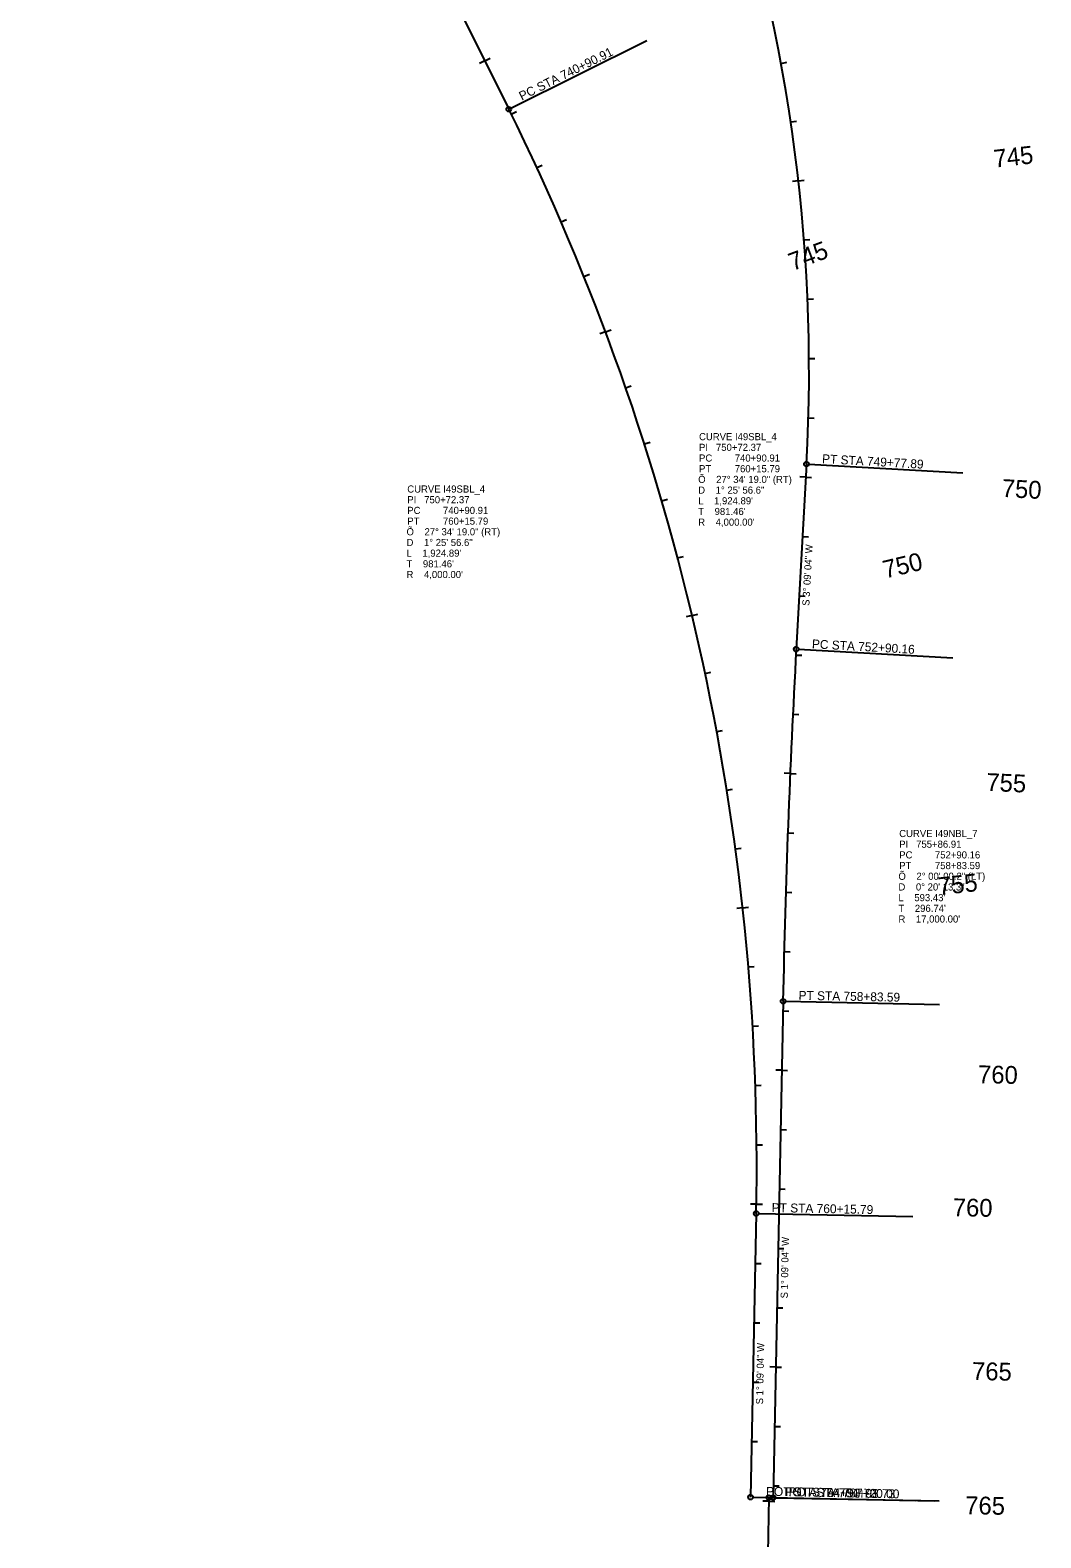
# Model space of a CAD drawing. Extents: x 2819977 to 2827606, y 116785 to 150320.
# Drawn here: x 2822516 to 2824219, y 142313 to 144853 of the extents above; entities that cross this region are included whole.
import ezdxf

# ---------------------------------------------------------------- set-up
doc = ezdxf.new("R2010")
doc.units = 0
for name, color, linetype in [('Default', 7, 'Continuous'), ('Modeling-Contours-Minor-Existing', 7, 'Continuous'), ('Modeling-Flow Arrows-Existing', 7, 'Continuous'), ('Modeling-Spot-Existing', 7, 'Continuous'), ('Modeling-Triangle Verticies-Existing', 7, 'Continuous')]:
    doc.layers.add(name, color=color, linetype=linetype)

msp = doc.modelspace()

# ---------------------------------------------------------------- linework, layer by layer
at = {"layer": 'Default'}
for p, q in [((2822515.7, 146343.3), (2823322.4, 144719.6)), ((2823824, 144121.8), (2823806.8, 143810))]:
    msp.add_line(p, q, dxfattribs=at)
for centre, radius, start, end in [((2820963.6, 144279.3), 2864.8, 356.8489, 41.5661), ((2819740.2, 142939.8), 4000, 358.849, 26.4209), ((2840781.1, 142875.6), 17000, 176.84893, 178.84897)]:
    msp.add_arc(centre, radius, start, end, dxfattribs=at)
at = {"layer": 'Modeling-Flow Arrows-Existing'}
for p, q in [((2822515.7, 146343.3), (2823322.4, 144719.6)), ((2823281.9, 144801), (2823273, 144796.6)), ((2823281.9, 144801), (2823290.9, 144805.5)), ((2823781.2, 144796.8), (2823791.1, 144798.6)), ((2823326.4, 144711.5), (2823335.4, 144715.9)), ((2823797.6, 144698.1), (2823807.5, 144699.6)), ((2823369.6, 144621.3), (2823378.7, 144625.5)), ((2823810.5, 144599), (2823800.5, 144597.9)), ((2823810.5, 144599), (2823820.4, 144600.1)), ((2823410.5, 144530), (2823419.7, 144534)), ((2823819.9, 144499.4), (2823829.8, 144500.2)), ((2823449.1, 144437.8), (2823458.4, 144441.5)), ((2823825.8, 144399.6), (2823835.8, 144400)), ((2823485.4, 144344.6), (2823476, 144341.1)), ((2823485.4, 144344.6), (2823494.7, 144348.1)), ((2823828.3, 144299.6), (2823838.3, 144299.7)), ((2823519.3, 144250.5), (2823528.8, 144253.8)), ((2823827.2, 144199.6), (2823837.2, 144199.4)), ((2823550.9, 144155.7), (2823560.4, 144158.7)), ((2823824, 144121.8), (2823806.8, 143810)), ((2823822.8, 144099.7), (2823812.8, 144100.3)), ((2823822.8, 144099.7), (2823832.8, 144099.2)), ((2823580.1, 144060), (2823589.7, 144062.8)), ((2823817.3, 143999.9), (2823827.3, 143999.3)), ((2823606.9, 143963.7), (2823616.6, 143966.2)), ((2823811.8, 143900.1), (2823821.8, 143899.5)), ((2823631.3, 143866.7), (2823621.6, 143864.4)), ((2823631.3, 143866.7), (2823641, 143869)), ((2823806.3, 143800.2), (2823816.3, 143799.7)), ((2823653.3, 143769.1), (2823663, 143771.2)), ((2823801.2, 143700.3), (2823811.2, 143699.8)), ((2823672.8, 143671.1), (2823682.6, 143672.9)), ((2823796.6, 143600.4), (2823786.6, 143600.9)), ((2823796.6, 143600.4), (2823806.6, 143600)), ((2823689.8, 143572.5), (2823699.7, 143574.1)), ((2823792.6, 143500.5), (2823802.6, 143500.1)), ((2823704.4, 143473.6), (2823714.3, 143474.9)), ((2823789.3, 143400.6), (2823799.2, 143400.3)), ((2823716.5, 143374.3), (2823706.6, 143373.3)), ((2823716.5, 143374.3), (2823726.5, 143375.4)), ((2823786.5, 143300.6), (2823796.5, 143300.4)), ((2823726.1, 143274.8), (2823736.1, 143275.6)), ((2823784.6, 143217), (2823767.8, 142380.8)), ((2823784.2, 143200.6), (2823794.2, 143200.4)), ((2823733.3, 143175.1), (2823743.2, 143175.7)), ((2823782.2, 143100.7), (2823772.2, 143100.9)), ((2823782.2, 143100.7), (2823792.2, 143100.5)), ((2823737.9, 143075.2), (2823747.9, 143075.5)), ((2823780.2, 143000.7), (2823790.2, 143000.5)), ((2823740, 142975.2), (2823750, 142975.3)), ((2823778.2, 142900.7), (2823788.2, 142900.5)), ((2823739.7, 142875.2), (2823729.7, 142875.4)), ((2823739.4, 142859.4), (2823729.8, 142381.6)), ((2823739.7, 142875.2), (2823749.7, 142875)), ((2823776.2, 142800.7), (2823786.2, 142800.5)), ((2823737.7, 142775.2), (2823747.7, 142775)), ((2823774.2, 142700.7), (2823784.2, 142700.5)), ((2823735.7, 142675.2), (2823745.7, 142675)), ((2823772.2, 142600.8), (2823762.2, 142601)), ((2823772.2, 142600.8), (2823782.2, 142600.6)), ((2823733.7, 142575.3), (2823743.7, 142575.1)), ((2823770.2, 142500.8), (2823780.2, 142500.6)), ((2823731.7, 142475.3), (2823741.7, 142475.1)), ((2823760.8, 142380.9), (2823701.1, 139408.5)), ((2823768.2, 142400.8), (2823778.2, 142400.6)), ((2823760.6, 142374.7), (2823750.6, 142374.9)), ((2823760.6, 142374.7), (2823770.6, 142374.5))]:
    msp.add_line(p, q, dxfattribs=at)
for centre, radius, start, end in [((2820963.6, 144279.3), 2864.8, 356.8489, 41.5661), ((2819740.2, 142939.8), 4000, 358.849, 26.4209), ((2840781.1, 142875.6), 17000, 176.84893, 178.84897)]:
    msp.add_arc(centre, radius, start, end, dxfattribs=at)
at = {"layer": 'Modeling-Spot-Existing'}
for p, q in [((2823326, 144721.4), (2823555.2, 144835.3)), ((2823828, 144121.6), (2824087.4, 144107.3)), ((2823810.8, 143809.8), (2824070.9, 143795.5)), ((2823788.6, 143217), (2824048.3, 143211.7)), ((2823743.4, 142859.3), (2824003.1, 142854.1)), ((2823733.8, 142381.5), (2824008.5, 142376)), ((2823764.8, 142380.9), (2824039.5, 142375.3)), ((2823771.8, 142380.7), (2824047.7, 142375.2))]:
    msp.add_line(p, q, dxfattribs=at)
for centre in [(2823322.4, 144719.6), (2823824, 144121.8), (2823806.8, 143810), (2823784.6, 143217), (2823739.4, 142859.4), (2823729.8, 142381.6), (2823760.8, 142380.9), (2823767.8, 142380.8)]:
    msp.add_circle(centre, 4, dxfattribs=at)

# ---------------------------------------------------------------- texts
at = {"layer": 'Modeling-Contours-Minor-Existing'}
for s, rotation, p in [('S 3%%d 09\' 04" W', 86.8489, (2823828.9, 143882.8)), ('S 1%%d 09\' 04" W', 88.849, (2823792.5, 142716.3)), ('S 1%%d 09\' 04" W', 88.849, (2823750.9, 142537.8))]:
    msp.add_text(s, height=12, rotation=rotation, dxfattribs=at).set_placement(p)
at = {"layer": 'Modeling-Flow Arrows-Existing'}
for s, rotation, p in [(' 745', 6.4068, (2824130.1, 144619.8)), (' 745', 20.5611, (2823790.3, 144442.9)), (' 750', 356.8489, (2824141.5, 144067.2)), (' 750', 13.3992, (2823946.1, 143926.3)), (' 755', 357.5561, (2824115.7, 143571.8)), (' 755', 6.2372, (2824036.2, 143394.2)), (' 760', 358.849, (2824101.9, 143079.2)), (' 760', 359.0752, (2824059.4, 142855)), (' 765', 358.849, (2824091.8, 142579.3)), (' 765', 358.849, (2824080.3, 142353.3))]:
    msp.add_text(s, height=30, rotation=rotation, dxfattribs=at).set_placement(p)
at = {"layer": 'Modeling-Spot-Existing'}
for s, rotation, p in [('PC STA 740+90.91', 26.4209, (2823344.3, 144733.9)), ('PT STA 749+77.89', 356.8489, (2823850.1, 144123.4)), ('PC STA 752+90.16', 356.8489, (2823833, 143811.6)), ('PT STA 758+83.59', 358.849, (2823810.6, 143219.5)), ('PT STA 760+15.79', 358.849, (2823765.4, 142861.9)), ('POT STA 764+93.73', 358.849, (2823755.8, 142384)), ('POT STA 764+93.73', 358.849, (2823786.8, 142383.4)), ('POT STA 767+20.00', 358.849, (2823793.8, 142383.3))]:
    msp.add_text(s, height=15, rotation=rotation, dxfattribs=at).set_placement(p)
at = {"layer": 'Modeling-Triangle Verticies-Existing'}
for s, p in [('CURVE I49SBL_4', (2823643, 144162)), ('PI   750+72.37', (2823643, 144144)), ('PC', (2823643, 144126)), ('740+90.91', (2823703.2, 144126)), ('Õ    27%%d 34\' 19.0" (RT)', (2823641.6, 144090)), ('PT', (2823643, 144108)), ('760+15.79', (2823703.2, 144108)), ('CURVE I49SBL_4', (2823151.3, 144073.8)), ('D    1%%d 25\' 56.6"', (2823641.6, 144072)), ('PI   750+72.37', (2823151.3, 144055.8)), ("L    1,924.89'", (2823641.6, 144054)), ('PC', (2823151.3, 144037.8)), ('PT', (2823151.3, 144019.8)), ('740+90.91', (2823211.5, 144037.8)), ('760+15.79', (2823211.5, 144019.8)), ("T    981.46'", (2823641.6, 144036)), ("R    4,000.00'", (2823641.6, 144018)), ('Õ    27%%d 34\' 19.0" (RT)', (2823150, 144001.8)), ('D    1%%d 25\' 56.6"', (2823150, 143983.8)), ("L    1,924.89'", (2823150, 143965.8)), ("T    981.46'", (2823150, 143947.8)), ("R    4,000.00'", (2823150, 143929.8)), ('CURVE I49NBL_7', (2823980.4, 143493.5)), ('PI   755+86.91', (2823980.4, 143475.5)), ('PC', (2823980.4, 143457.5)), ('752+90.16', (2824040.6, 143457.5)), ('PT', (2823980.4, 143439.5)), ('758+83.59', (2824040.6, 143439.5)), ('Õ    2%%d 00\' 00.2" (LT)', (2823979.1, 143421.5)), ('D    0%%d 20\' 13.3"', (2823979.1, 143403.5)), ("L    593.43'", (2823979.1, 143385.5)), ("T    296.74'", (2823979.1, 143367.5)), ("R    17,000.00'", (2823979.1, 143349.5))]:
    msp.add_text(s, height=12, dxfattribs=at).set_placement(p)

doc.saveas('drawing.dxf')
